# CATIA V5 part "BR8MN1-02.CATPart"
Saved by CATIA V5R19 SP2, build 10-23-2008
Part number: BR8MN1-02
Definition: design
Nomenclature: BR8MN1-02
Source: Unknown
Bounding box of the stored display mesh (mm): x -4.6 to 7.9, y 0 to 12, z 0 to 10.16
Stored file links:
  Z:\fausse table rondelle-20220905T211342Z-001\fausse table rondelle\BR8MN1-02.CATPart
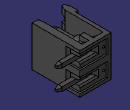
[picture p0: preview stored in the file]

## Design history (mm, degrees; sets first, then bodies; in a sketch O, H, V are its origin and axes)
AxisSystem1: origin (0, 0, 0), X (1, 0, 0), Y (0, 1, 0), Z (0, 0, 1)
Body1 "MANIFOLD_SOLID_BREP #164119" (main body)
  Solid1: solid without history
